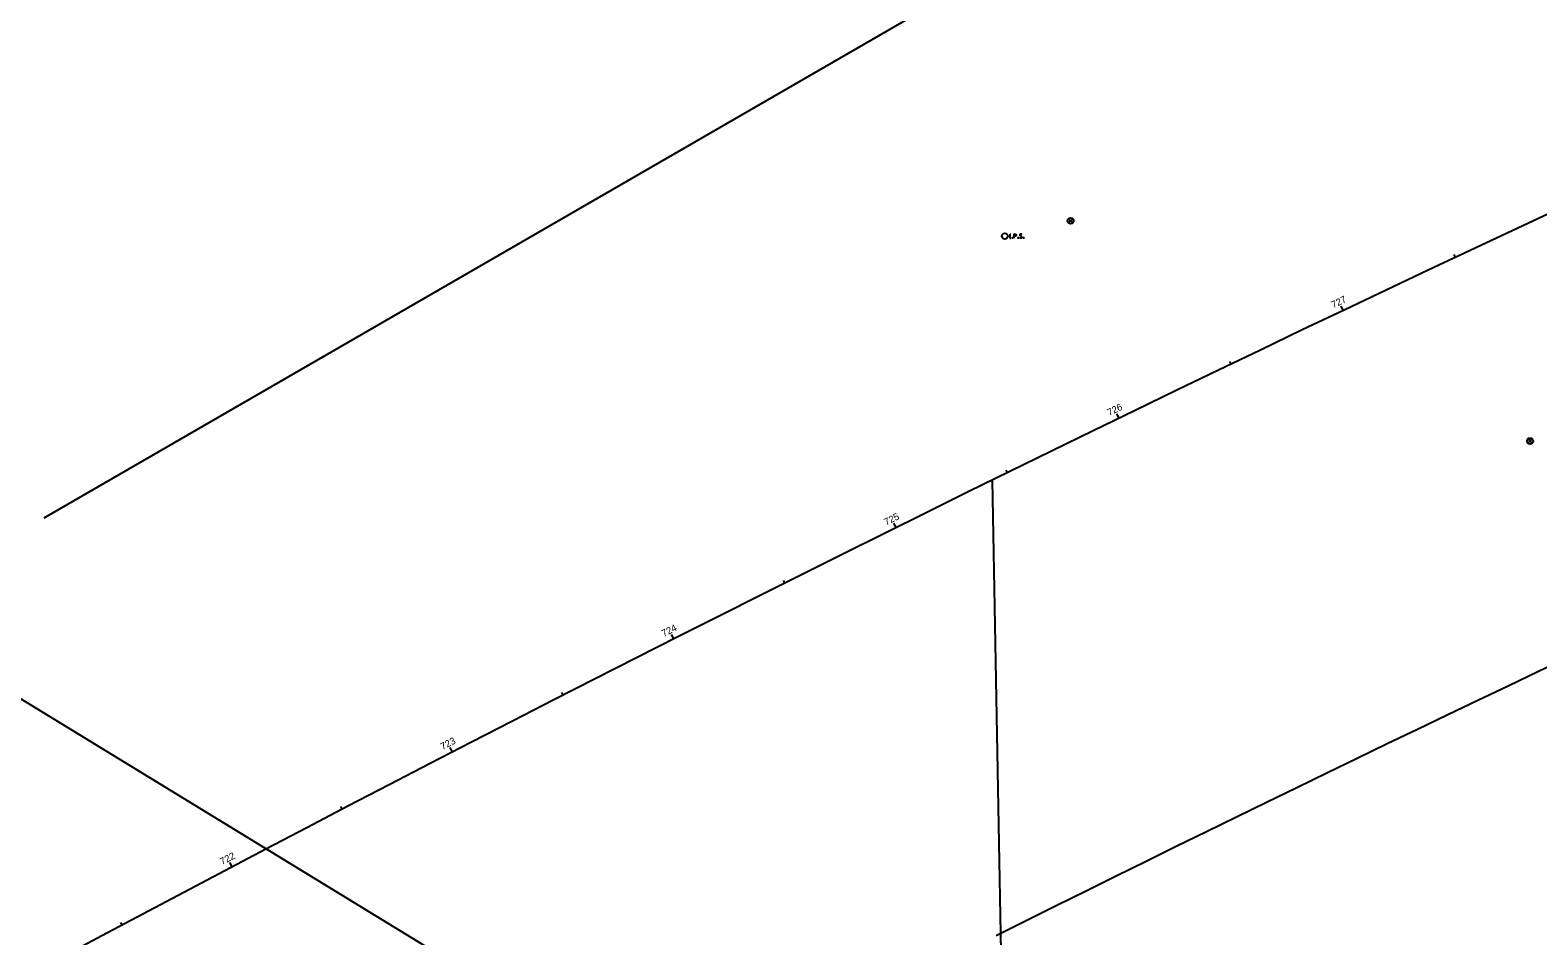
# Model space of a CAD drawing. Extents: x 197895 to 201888, y 454260 to 456995.
# Drawn here: x 200672 to 201279, y 456346 to 456710 of the extents above; entities that cross this region are included whole.
import ezdxf

# ---------------------------------------------------------------- set-up
doc = ezdxf.new("R2010")
doc.units = 0
for name, color, linetype in [('PF_P_Grade_Line', 7, 'Continuous'), ('PF_X_Ground_Line', 7, 'Continuous'), ('PV_X_EOP', 7, 'Continuous'), ('RW_P_Const_Limits', 7, 'Continuous'), ('RW_X_CL_100_Stations', 7, 'Continuous'), ('SH_Text', 7, 'Continuous'), ('VG_P_Text', 7, 'Continuous')]:
    doc.layers.add(name, color=color, linetype=linetype)

msp = doc.modelspace()

# ---------------------------------------------------------------- linework, layer by layer
at = {"layer": 'PF_P_Grade_Line'}
for centre in [(201164.4, 456580.38), (200767.12, 456380.85)]:
    msp.add_circle(centre, 0.05, dxfattribs=at)
at = {"layer": 'PF_X_Ground_Line'}
for points in [[(201066.23, 456628.28), (201066.58, 456628.28)], [(201066.41, 456626.68), (201066.41, 456628.28)], [(201067.37, 456626.89), (201067.42, 456626.89), (201067.45, 456626.87), (201067.49, 456626.82), (201067.49, 456626.76), (201067.45, 456626.71), (201067.42, 456626.68), (201067.37, 456626.68), (201067.33, 456626.71), (201067.3, 456626.76), (201067.3, 456626.82), (201067.33, 456626.87), (201067.37, 456626.89)], [(201067.97, 456626.68), (201067.97, 456628.28), (201068.5, 456628.28), (201068.56, 456628.27), (201068.63, 456628.24), (201068.67, 456628.22), (201068.7, 456628.19), (201068.74, 456628.13), (201068.78, 456628.07), (201068.8, 456627.97), (201068.8, 456627.81), (201068.79, 456627.76), (201068.77, 456627.69), (201068.72, 456627.6), (201068.68, 456627.56), (201068.65, 456627.54), (201068.59, 456627.51), (201068.5, 456627.5), (201067.97, 456627.5)], [(201069.62, 456626.89), (201069.67, 456626.89), (201069.7, 456626.87), (201069.74, 456626.82), (201069.74, 456626.76), (201069.7, 456626.71), (201069.67, 456626.68), (201069.62, 456626.68), (201069.58, 456626.71), (201069.55, 456626.76), (201069.55, 456626.82), (201069.58, 456626.87), (201069.62, 456626.89)], [(201070.98, 456628.17), (201070.96, 456628.19), (201070.93, 456628.22), (201070.83, 456628.26), (201070.71, 456628.28), (201070.62, 456628.28), (201070.59, 456628.28), (201070.44, 456628.24), (201070.32, 456628.17), (201070.24, 456628.07), (201070.22, 456627.97), (201070.22, 456627.89), (201070.24, 456627.79), (201070.33, 456627.7), (201070.94, 456627.32), (201070.99, 456627.27), (201071.02, 456627.22), (201071.04, 456627.15), (201071.04, 456627.07), (201071.03, 456627), (201071.02, 456626.95), (201070.99, 456626.88), (201070.97, 456626.83), (201070.95, 456626.79), (201070.92, 456626.76), (201070.88, 456626.73), (201070.84, 456626.71), (201070.81, 456626.69), (201070.71, 456626.68), (201070.55, 456626.68), (201070.45, 456626.71), (201070.31, 456626.79), (201070.22, 456626.87)], [(201071.8, 456626.89), (201071.85, 456626.89), (201071.89, 456626.87), (201071.92, 456626.82), (201071.92, 456626.76), (201071.89, 456626.71), (201071.85, 456626.68), (201071.8, 456626.68), (201071.76, 456626.71), (201071.73, 456626.76), (201071.73, 456626.82), (201071.76, 456626.87), (201071.8, 456626.89)], [(201066.23, 456626.68), (201066.58, 456626.68)]]:
    msp.add_lwpolyline(points, dxfattribs=at)
msp.add_circle((201064.21, 456627.48), 1.2, dxfattribs=at)
at = {"layer": 'PV_X_EOP'}
msp.add_line((201059.18, 456529.27), (201065.22, 456198.75), dxfattribs=at)
at = {"layer": 'RW_P_Const_Limits'}
for p, q in [((201091.53, 456632.81), (201089.84, 456634.5)), ((201089.84, 456632.81), (201091.53, 456634.5)), ((201276.4, 456544.16), (201274.7, 456545.86)), ((201274.7, 456544.16), (201276.4, 456545.86))]:
    msp.add_line(p, q, dxfattribs=at)
for centre in [(201090.69, 456633.65), (201275.55, 456545.01)]:
    msp.add_circle(centre, 1.2, dxfattribs=at)
at = {"layer": 'RW_X_CL_100_Stations'}
for p, q in [((201245.55, 456618.94), (201245.03, 456620.03)), ((201200.35, 456597.55), (201199.49, 456599.36)), ((201155.24, 456575.98), (201154.72, 456577.06)), ((201110.23, 456554.22), (201109.35, 456556.02)), ((201065.3, 456532.28), (201064.77, 456533.36)), ((201020.46, 456510.16), (201019.57, 456511.95)), ((200975.71, 456487.85), (200975.17, 456488.93)), ((200931.05, 456465.37), (200930.15, 456467.15)), ((200886.48, 456442.7), (200885.94, 456443.77)), ((200842.01, 456419.85), (200841.09, 456421.62)), ((200797.63, 456396.82), (200797.08, 456397.88)), ((200753.35, 456373.6), (200752.41, 456375.37)), ((200709.16, 456350.21), (200708.59, 456351.27))]:
    msp.add_line(p, q, dxfattribs=at)
at = {"layer": 'SH_Text'}
msp.add_line((201033.58, 456218.07), (200482.42, 456554.77), dxfattribs=at)
msp.add_arc((206475.15, 445510.73), 12277.67, 112.039489, 134.330526, dxfattribs=at)
at = {"layer": 'VG_P_Text'}
msp.add_line((200677.78, 456514.05), (201063.88, 456737.31), dxfattribs=at)
msp.add_arc((206475.15, 445510.73), 12112.67, 112.468785, 116.55179, dxfattribs=at)

# ---------------------------------------------------------------- texts
at = {"layer": 'RW_X_CL_100_Stations'}
for s, rotation, p in [('727', 25.44378, (201196.35, 456598.41)), ('726', 25.91045, (201106.21, 456555.05)), ('725', 26.37712, (201016.47, 456510.97)), ('724', 26.84378, (200927, 456466.12)), ('723', 27.31045, (200838.02, 456420.6)), ('722', 27.77712, (200749.34, 456374.32))]:
    msp.add_text(s, height=2.8, rotation=rotation, dxfattribs=at).set_placement(p)

doc.saveas('drawing.dxf')
